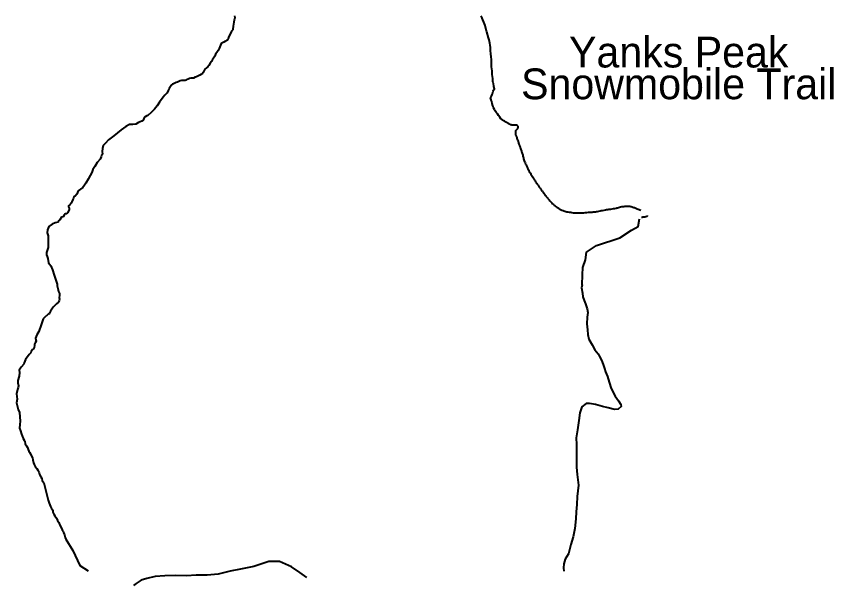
# Model space of a CAD drawing. Extents: x 322505 to 642419, y 5806860 to 5919753.
# Drawn here: x 606220 to 614195, y 5859504 to 5865060 of the extents above; entities that cross this region are included whole.
import ezdxf
from ezdxf.enums import TextEntityAlignment as Align

# ---------------------------------------------------------------- set-up
doc = ezdxf.new("R2010")
doc.units = 0
doc.header["$LTSCALE"] = 140
doc.layers.add('4', color=7, linetype='Continuous', lineweight=40)
doc.layers.add('5', color=7, linetype='Continuous', lineweight=40)

msp = doc.modelspace()

# ---------------------------------------------------------------- linework, layer by layer
at = {"layer": '4'}
for points in [[(608349, 5865066.5), (608351.1, 5865044.6), (608349, 5865033.7), (608344.3, 5865025.2), (608340.5, 5865003), (608336.7, 5864965.4), (608334.5, 5864954), (608331.3, 5864942), (608333.4, 5864930), (608319.9, 5864914.9), (608311.7, 5864899.5), (608295.1, 5864869.4), (608288.9, 5864854.1), (608286.3, 5864842.7), (608282.6, 5864831.9), (608279.6, 5864828), (608269.3, 5864824.3), (608259.7, 5864818.5), (608245, 5864809.7), (608230, 5864801), (608219.7, 5864793.7), (608212.3, 5864778.1), (608205.6, 5864762.4), (608198, 5864746.4), (608189.2, 5864726.3), (608175.3, 5864708.7), (608164.2, 5864690.3), (608156.6, 5864671), (608143.2, 5864653.7), (608133.9, 5864639.6)], [(608133.9, 5864639.6), (608123.1, 5864620.7), (608111.9, 5864602.7), (608097.2, 5864580.5), (608087.3, 5864568.6), (608075.7, 5864557.1), (608059.4, 5864543.4), (608047.9, 5864525.9), (608041.4, 5864511.7), (608035.1, 5864504), (608026.4, 5864497), (608008.8, 5864486.6), (607991.6, 5864475.2), (607978, 5864470.8), (607963.8, 5864465.9), (607949.9, 5864458.5), (607933.8, 5864458.1), (607920.8, 5864456.5), (607911, 5864453.6), (607897.7, 5864447.9), (607884, 5864442.4), (607874.4, 5864437.5), (607867.9, 5864434.6), (607859.8, 5864433.2), (607848, 5864433.7), (607836.9, 5864434.7), (607829.8, 5864433.8), (607817.9, 5864429.9), (607804.9, 5864424.4), (607791.5, 5864419.2), (607780.9, 5864413.8), (607765.9, 5864407.7), (607754.2, 5864402.3), (607742.6, 5864398.4), (607735.1, 5864393), (607730.6, 5864386.1), (607724.2, 5864376.4), (607717.4, 5864366), (607712.5, 5864356), (607707, 5864344.4)], [(607707, 5864344.4), (607702.6, 5864334.8), (607686.8, 5864311.8), (607668.2, 5864292.4), (607651.8, 5864272.9), (607617.4, 5864222), (607593.6, 5864185.9), (607566.7, 5864153.6), (607552.8, 5864139.4), (607536.4, 5864120.3), (607504, 5864093.5), (607494.1, 5864088.1), (607477.5, 5864078.9), (607462.2, 5864061.9), (607456.9, 5864048.2), (607443.6, 5864038.3), (607412.9, 5864023.3), (607387.1, 5864007.1), (607357.7, 5864006.3), (607322.4, 5864005.5), (607289.5, 5863985.6), (607243.8, 5863953.6), (607172.4, 5863894), (607120.5, 5863856.2), (607089.5, 5863824.1), (607066.8, 5863799.6), (607061.1, 5863768.9), (607058.7, 5863740.5), (607059.6, 5863715.9), (607051.4, 5863700.7), (607048.4, 5863690.1), (607037.1, 5863667.3), (607008.9, 5863635.3), (606985.3, 5863595.3), (606965, 5863564.2), (606955.4, 5863537.7), (606941.1, 5863507.7), (606921, 5863470.4), (606899.3, 5863432.7), (606883.4, 5863411.8), (606867.9, 5863389.1), (606823.7, 5863355.8), (606809, 5863325.8), (606794.6, 5863305.5), (606782.1, 5863299.4), (606776.8, 5863285.8), (606769.6, 5863271.8), (606762, 5863251.1), (606754.6, 5863238.2), (606743.5, 5863222.7), (606729.7, 5863210.6), (606729.8, 5863200.5), (606734.5, 5863186.6), (606735, 5863170.3), (606717.7, 5863141.2), (606706.7, 5863134.1), (606696.9, 5863134), (606687.3, 5863121.2), (606676.4, 5863103.4), (606661.1, 5863098.8), (606644.9, 5863074.2), (606631, 5863063.5), (606627.2, 5863052), (606597.3, 5863044.4), (606567.8, 5863031.4), (606535.9, 5863010.5), (606524.4, 5862977.6), (606520.7, 5862947.1), (606524.2, 5862938.7), (606531.2, 5862919.6), (606529.5, 5862867.9), (606528.7, 5862803.2), (606513.5, 5862756.6), (606513.9, 5862733.5), (606521.2, 5862718), (606526, 5862697.9), (606533.9, 5862655.9), (606546.4, 5862638.8), (606555.3, 5862624.4), (606573.8, 5862586), (606574.4, 5862575.2), (606584.6, 5862543.5), (606609.2, 5862476), (606618, 5862446.5), (606617.9, 5862430.2), (606626.3, 5862390.3), (606632.4, 5862375.7), (606640.5, 5862354.7), (606641.9, 5862334.3), (606638.7, 5862315.7), (606642.3, 5862300.4)], [(606642.3, 5862300.4), (606639.2, 5862285.8), (606629.9, 5862272.3), (606610, 5862254.2), (606580.6, 5862221.4), (606551.5, 5862183.5), (606546.1, 5862171.4), (606544.8, 5862155.8), (606533.3, 5862156.4), (606489.2, 5862116), (606482.5, 5862107.2), (606463.8, 5862060.1), (606462.9, 5862049), (606439.8, 5861983.9), (606420.8, 5861950.9), (606408.3, 5861918.1), (606413.1, 5861890.5), (606402.8, 5861875.4), (606397.5, 5861859.6), (606397, 5861848.8), (606394.4, 5861826.9), (606387.2, 5861813.7), (606378.2, 5861807.4), (606363.9, 5861788.7), (606360.4, 5861776.3), (606344.9, 5861758.8), (606308.2, 5861710.2), (606302.3, 5861694.9), (606294.6, 5861680), (606292.3, 5861664.3), (606265.7, 5861634.8), (606248.5, 5861608.1), (606250.6, 5861583.6), (606247.9, 5861549), (606235, 5861505.5), (606232.9, 5861483.6), (606239.8, 5861454), (606238.3, 5861437.9), (606230.3, 5861419.1), (606219.8, 5861377.7), (606226.2, 5861322.8), (606222.4, 5861289.6), (606236.9, 5861223.4), (606250.1, 5861194.1), (606255.6, 5861110.8), (606253.6, 5861076.6), (606251.6, 5861040.9), (606260.4, 5861016.5), (606271.2, 5860983), (606275.4, 5860965.2), (606287.3, 5860938.7), (606297.3, 5860923.7), (606301.2, 5860912.9), (606307.3, 5860889.2), (606319.2, 5860867.7), (606327.7, 5860851.2), (606334.6, 5860833.9), (606340.6, 5860816.7), (606347.8, 5860807.1), (606357.1, 5860791.9), (606365.5, 5860775), (606376.4, 5860752.3), (606381.7, 5860732.3), (606387.7, 5860703.4), (606392.4, 5860686.9), (606405, 5860667.4), (606420.1, 5860648), (606429.3, 5860632.2), (606442.9, 5860604.9), (606447.3, 5860587.8), (606457.7, 5860566.8), (606467.4, 5860548.8), (606472.2, 5860531.6), (606487.6, 5860508.7), (606528.4, 5860351.9), (606529, 5860339.3), (606539.8, 5860308.4), (606554.1, 5860275.5), (606561.4, 5860256.7), (606572.8, 5860244.6), (606574.5, 5860233), (606576.7, 5860221.4), (606585.4, 5860202.1), (606595.6, 5860184.6), (606610.3, 5860162.9), (606622.7, 5860140.1), (606634.9, 5860118.9), (606645.1, 5860093.8), (606656.8, 5860070.1), (606667.4, 5860050.2), (606676.6, 5860034.3), (606680.6, 5860024.3), (606689.1, 5859998.7), (606696.7, 5859973.7), (606704.2, 5859959), (606770.6, 5859848.1), (606837.8, 5859700.1), (606921.8, 5859649.5)]]:
    msp.add_lwpolyline(points, dxfattribs=at)
at = {"layer": '5'}
for points in [[(610765.2, 5865042), (610753.5, 5865061)], [(611093, 5863939), (611093, 5863940), (611095, 5863945), (611097, 5863949), (611099, 5863952), (611102, 5863955), (611106, 5863959), (611109, 5863962), (611112, 5863966), (611114, 5863970), (611116, 5863974), (611116, 5863978), (611116, 5863979), (611116, 5863981), (611115, 5863983), (611115, 5863986), (611114, 5863988), (611112, 5863991), (611111, 5863993), (611109, 5863995), (611106, 5863996), (611104, 5863997), (611099, 5863998), (611094, 5863998), (611089, 5863998), (611085, 5863998), (611081, 5863997), (611077, 5863997), (611073, 5863997), (611069, 5863997), (611064, 5863997), (611059, 5863998), (611053, 5863998), (611048, 5864000), (611043, 5864001), (611039, 5864003), (611035, 5864005), (611029, 5864008), (611024, 5864011), (611018, 5864014), (611014, 5864017), (611009, 5864020), (611006, 5864022), (611001, 5864025), (610996, 5864028), (610990, 5864032), (610983, 5864036), (610975, 5864041), (610967, 5864046), (610960, 5864051), (610954, 5864055), (610948, 5864059), (610936, 5864077), (610925, 5864093), (610914, 5864108), (610905, 5864120), (610898, 5864129), (610891, 5864138), (610884, 5864152), (610877, 5864168), (610873, 5864181), (610870, 5864188), (610864, 5864210), (610858, 5864228), (610854, 5864243), (610854, 5864245), (610851, 5864256), (610847.6, 5864266.5), (610848.6, 5864268.5), (610854.7, 5864281.5), (610862.1, 5864296.5), (610867.1, 5864303), (610870.6, 5864317), (610871.8, 5864328.5), (610876.7, 5864338.5), (610884, 5864354), (610879.9, 5864375.5), (610874.3, 5864407), (610873, 5864410.5), (610870.2, 5864427), (610869.8, 5864452.5), (610862.8, 5864491.5), (610863.9, 5864501.5), (610863.5, 5864528), (610857.8, 5864568.5), (610857.2, 5864601), (610857, 5864616.5), (610855.4, 5864640.5), (610852.4, 5864664.5), (610848.1, 5864696), (610845.1, 5864728.5), (610845.9, 5864756.5), (610841.8, 5864778), (610840.1, 5864799.5), (610832.1, 5864829.5), (610827.9, 5864851), (610809.2, 5864910), (610807.8, 5864916.5), (610793, 5864971.5), (610788.9, 5864988), (610765.2, 5865042)], [(611093, 5863939), (611092, 5863936), (611092, 5863932), (611092, 5863929), (611092, 5863925), (611092, 5863922), (611092, 5863919), (611092, 5863915), (611092, 5863910), (611092, 5863906), (611092, 5863902), (611093, 5863896), (611096, 5863890), (611099, 5863883), (611102, 5863877), (611105, 5863869), (611108, 5863861), (611111, 5863853), (611112, 5863847), (611115, 5863840), (611117, 5863834), (611119, 5863828), (611121, 5863821), (611124, 5863814), (611127, 5863807), (611129, 5863801), (611131, 5863796), (611133, 5863790), (611135, 5863785), (611137, 5863778), (611140, 5863771), (611143, 5863761), (611146, 5863753), (611148, 5863746), (611150, 5863738), (611152, 5863731), (611155, 5863723), (611158, 5863714), (611161, 5863705), (611163, 5863696), (611166, 5863687), (611168, 5863678), (611170, 5863670), (611173, 5863661), (611176, 5863651), (611180, 5863641), (611185, 5863629), (611189, 5863619), (611194, 5863610), (611198, 5863601), (611201, 5863594), (611204, 5863587), (611208, 5863579), (611211, 5863571), (611216, 5863563), (611220, 5863554), (611225, 5863545), (611230, 5863537), (611236, 5863529), (611241, 5863520), (611247, 5863510), (611253, 5863501), (611259, 5863491), (611264, 5863482), (611269, 5863475), (611273, 5863468), (611276, 5863462), (611281, 5863455), (611286, 5863446), (611292, 5863438), (611298, 5863429), (611303, 5863423), (611307, 5863417), (611310, 5863412), (611314, 5863406), (611319, 5863400), (611322, 5863394), (611327, 5863388), (611331, 5863382), (611334, 5863377), (611337, 5863373), (611341, 5863368), (611345, 5863362), (611350, 5863356), (611355, 5863350), (611360, 5863343), (611366, 5863335), (611371, 5863327), (611377, 5863320), (611382, 5863312), (611387, 5863306), (611392, 5863299), (611398, 5863292), (611404, 5863286), (611409, 5863280), (611413, 5863275)], [(611413, 5863275), (611419, 5863268), (611427, 5863260), (611435, 5863251), (611445, 5863241), (611453, 5863231), (611460, 5863225), (611467, 5863219), (611473, 5863213), (611481, 5863207), (611488, 5863201), (611496, 5863196), (611504, 5863191), (611512, 5863186), (611518, 5863182), (611523, 5863179), (611529, 5863176), (611536, 5863173), (611544, 5863169), (611554, 5863165), (611563, 5863162), (611572, 5863160), (611580, 5863157), (611590, 5863154), (611601, 5863152), (611614, 5863149), (611629, 5863148), (611641, 5863146), (611652, 5863144), (611662, 5863143), (611671, 5863142), (611680, 5863142), (611691, 5863141), (611701, 5863141), (611712, 5863141), (611721, 5863141), (611730, 5863142), (611739, 5863142), (611747, 5863143), (611758, 5863144), (611770, 5863145), (611787, 5863146), (611802, 5863148), (611814, 5863148), (611826, 5863149), (611838, 5863149), (611848, 5863151), (611859, 5863152), (611870, 5863154), (611881, 5863155), (611892, 5863157), (611904, 5863160), (611915, 5863162), (611927, 5863164), (611940, 5863167), (611955, 5863170), (611968, 5863172), (611979, 5863174), (611990, 5863175), (612000, 5863177), (612010, 5863178), (612022, 5863180), (612035, 5863182), (612048, 5863184), (612060, 5863186), (612072, 5863189), (612080, 5863191), (612087, 5863193), (612095, 5863196), (612105, 5863198), (612116, 5863200), (612129, 5863203), (612140, 5863205), (612149, 5863206), (612158, 5863207), (612168, 5863208), (612175, 5863209), (612181, 5863209), (612188, 5863209), (612195, 5863208), (612201, 5863208), (612208, 5863207), (612214, 5863206), (612220, 5863204), (612228, 5863202), (612236, 5863199), (612244, 5863196), (612252, 5863194), (612258, 5863191), (612264, 5863189), (612270, 5863186), (612278, 5863183), (612279, 5863183), (612287, 5863180), (612296, 5863176), (612304, 5863173), (612312, 5863169)], [(612376, 5863115), (612376, 5863113), (612375, 5863109), (612372, 5863106), (612368, 5863104), (612364, 5863102), (612360, 5863102), (612357, 5863101), (612352, 5863101), (612346, 5863100), (612339, 5863099), (612333, 5863099), (612327, 5863098), (612321, 5863097)], [(611739.8, 5862440.3), (611744.5, 5862537.4), (611746.7, 5862609.9), (611772.1, 5862683.9), (611783.4, 5862757.8), (611880.8, 5862823.5), (612108.1, 5862899.8), (612223.5, 5862972.2), (612288.9, 5863007.9), (612301.4, 5863085.6)], [(611739.8, 5862440.3), (611732.9, 5862411.4), (611744.2, 5862359.1), (611747.4, 5862324.2), (611760.3, 5862286.1), (611773.2, 5862254.4), (611789.2, 5862205.2), (611795.7, 5862168.7), (611789.2, 5862124.3), (611786, 5862057.7), (611792.5, 5862002.2), (611797.3, 5861954.6), (611807, 5861910.2), (611837.5, 5861853.1), (611863.3, 5861807), (611895.5, 5861765.8), (611906.7, 5861746.8), (611929.3, 5861703.9), (611947, 5861662.7), (611958.2, 5861623), (611967.9, 5861591.3), (611988.8, 5861546.9)], [(611988.8, 5861546.9), (612003.5, 5861489.4), (612025.4, 5861429.4), (612064.4, 5861352.6), (612096, 5861306.9), (612118, 5861273.3), (612120.4, 5861251.7), (612093.6, 5861225.3), (612057.1, 5861222.9), (611996.2, 5861239.7), (611937.7, 5861251.7), (611869.5, 5861270.9), (611811, 5861280.5), (611779.4, 5861280.5), (611737.9, 5861249.3), (611718.5, 5861189.3), (611708.7, 5861117.2), (611694.1, 5861023.6), (611681.9, 5860946.7), (611684.4, 5860881.9), (611684.4, 5860757), (611684.4, 5860660.9), (611691.7, 5860588.9), (611703.8, 5860483.2), (611691.7, 5860375.2)], [(611691.7, 5860375.2), (611687.7, 5860296.3), (611682.6, 5860223.5), (611680.1, 5860155.7), (611669.9, 5860060.4), (611652.1, 5859980.1), (611631.7, 5859904.8), (611606.3, 5859814.5), (611575.7, 5859761.8), (611563, 5859716.6), (611557.9, 5859676.4), (611563, 5859643.8)], [(609053.8, 5859584), (608987.6, 5859632.1), (608904, 5859689.2), (608788.2, 5859739.9), (608682.1, 5859739.9), (608537.4, 5859692.4), (608405.6, 5859663.8), (608305.9, 5859644.8), (608190.1, 5859616.3), (608080.8, 5859606.8), (607974.7, 5859606.8), (607881.5, 5859600.4), (607768.9, 5859603.6), (607669.2, 5859600.4), (607572.8, 5859594.1), (607492.4, 5859575.1), (607437.7, 5859556.1), (607388.6, 5859526), (607364.4, 5859504)]]:
    msp.add_lwpolyline(points, dxfattribs=at)

# ---------------------------------------------------------------- texts
for s, p in [('Yanks Peak', (612683.3, 5864561.4)), ('Snowmobile Trail', (612683.3, 5864251.4))]:
    msp.add_text(s, height=300, dxfattribs=at).set_placement(p, align=Align.CENTER)

doc.saveas('drawing.dxf')
